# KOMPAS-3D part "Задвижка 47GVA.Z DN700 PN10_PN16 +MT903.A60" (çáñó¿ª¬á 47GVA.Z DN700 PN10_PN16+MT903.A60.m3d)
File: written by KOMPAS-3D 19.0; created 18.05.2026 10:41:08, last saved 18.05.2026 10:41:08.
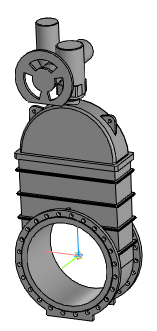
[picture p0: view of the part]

Document properties: Автор: Энергия; Полное имя файла: ..\Задвижка 47GVA.Z DN350_DN1200+MT903.A\Задвижка 47GVA.Z DN700 PN10_PN16+MT903.A60.a3d

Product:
- Part/product: Задвижка 47GVA.Z DN700 PN10_PN16 +MT903.A60
    Масса: 2375.01
  - Body: Электропривод МТ903.А60 без блока управления
      Масса: 346.451
  - Body: Задвижка 47GVA.Z DN700 PN10_PN16 без исполнит. мех.
      Масса: 2028.56

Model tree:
1. Операция без истории:1
2. Операция без истории:2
